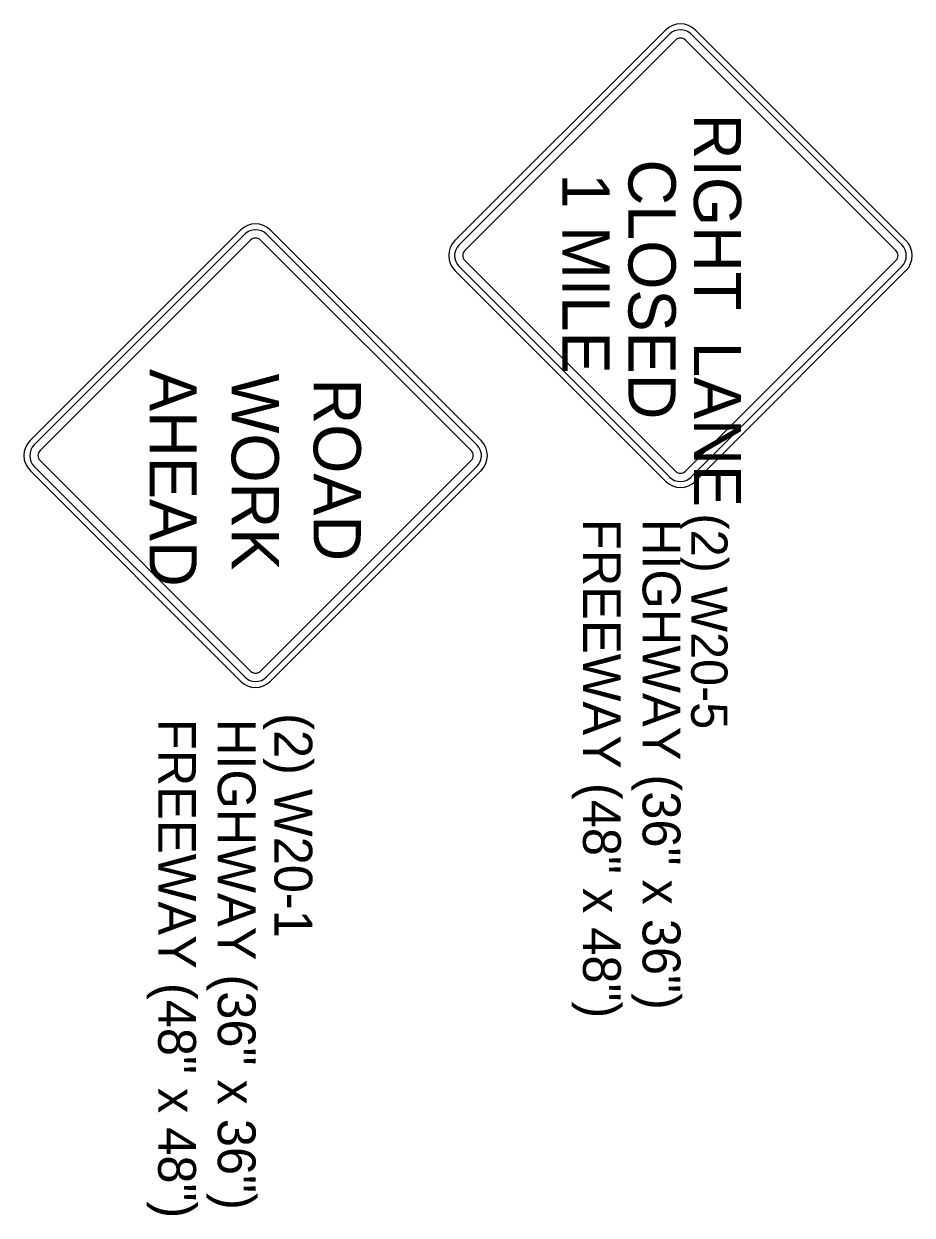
# Model space of a CAD drawing. Extents: x 1930579 to 1937521, y 596183 to 597566.
# Drawn here: x 1933840.4 to 1933981.4, y 596930.8 to 597119.9 of the extents above; entities that cross this region are included whole.
import ezdxf

# ---------------------------------------------------------------- set-up
doc = ezdxf.new("R2010")
doc.units = 0
doc.layers.add('P_TC_Signs_Temporary', color=7, linetype='Continuous')
doc.layers.add('R_Annotation', color=7, linetype='Continuous')

msp = doc.modelspace()

# ---------------------------------------------------------------- linework, layer by layer
at = {"layer": 'P_TC_Signs_Temporary'}
for p, q in [((1933908.78, 597085.51), (1933942.19, 597118.92)), ((1933909.45, 597084.85), (1933942.86, 597118.26)), ((1933910.37, 597083.92), (1933943.78, 597117.33)), ((1933945.38, 597117.33), (1933978.79, 597083.92)), ((1933946.3, 597118.26), (1933979.71, 597084.85)), ((1933946.97, 597118.92), (1933980.38, 597085.51)), ((1933841.35, 597053.77), (1933874.76, 597087.18)), ((1933879.54, 597087.18), (1933912.95, 597053.77)), ((1933842.01, 597053.11), (1933875.43, 597086.52)), ((1933842.94, 597052.18), (1933876.35, 597085.59)), ((1933877.94, 597085.59), (1933911.35, 597052.18)), ((1933878.87, 597086.52), (1933912.28, 597053.11)), ((1933942.86, 597047.99), (1933909.45, 597081.4)), ((1933943.78, 597048.92), (1933910.37, 597082.33)), ((1933978.79, 597082.33), (1933945.38, 597048.92)), ((1933979.71, 597081.4), (1933946.3, 597047.99)), ((1933942.19, 597047.33), (1933908.78, 597080.74)), ((1933980.38, 597080.74), (1933946.97, 597047.33)), ((1933875.43, 597016.25), (1933842.01, 597049.66)), ((1933876.35, 597017.18), (1933842.94, 597050.59)), ((1933911.35, 597050.59), (1933877.94, 597017.18)), ((1933912.28, 597049.66), (1933878.87, 597016.25)), ((1933874.76, 597015.58), (1933841.35, 597049)), ((1933912.95, 597049), (1933879.54, 597015.58))]:
    msp.add_line(p, q, dxfattribs=at)
for centre, radius, start, end in [((1933944.58, 597116.53), 3.37, 45, 135), ((1933944.58, 597116.53), 2.44, 45, 135), ((1933944.58, 597116.53), 1.12, 45, 135), ((1933877.15, 597084.79), 3.37, 45, 135), ((1933877.15, 597084.79), 2.44, 45, 135), ((1933877.15, 597084.79), 1.12, 45, 135), ((1933911.17, 597083.12), 3.37, 135, 225), ((1933977.99, 597083.12), 3.38, 315, 45), ((1933911.17, 597083.12), 2.44, 135, 225), ((1933911.17, 597083.12), 1.13, 135, 225), ((1933977.99, 597083.12), 1.13, 315, 45), ((1933977.99, 597083.12), 2.44, 315, 45), ((1933843.74, 597051.38), 3.37, 135, 225), ((1933843.74, 597051.38), 2.44, 135, 225), ((1933910.56, 597051.38), 2.44, 315, 45), ((1933910.56, 597051.38), 3.38, 315, 45), ((1933843.74, 597051.38), 1.13, 135, 225), ((1933910.56, 597051.38), 1.13, 315, 45), ((1933944.58, 597049.71), 3.38, 225, 315), ((1933944.58, 597049.71), 2.44, 225, 315), ((1933944.58, 597049.71), 1.12, 225, 315), ((1933877.15, 597017.97), 1.12, 225, 315), ((1933877.15, 597017.97), 3.38, 225, 315), ((1933877.15, 597017.97), 2.44, 225, 315)]:
    msp.add_arc(centre, radius, start, end, dxfattribs=at)

# ---------------------------------------------------------------- texts
for s, p in [('RIGHT\u2002LANE', (1933946.71, 597105.64)), ('CLOSED', (1933936.33, 597098.38)), ('1 MILE', (1933925.83, 597096.17)), (' AHEAD ', (1933860.32, 597067.92)), ('WORK', (1933873.34, 597064.37)), (' ROAD ', (1933886.36, 597066.4))]:
    msp.add_text(s, height=7.5, rotation=270, dxfattribs=at).set_placement(p)
at = {"layer": 'R_Annotation'}
for s, height, p in [('(2) W20-5', 5.76, (1933946.29, 597042.2)), ('FREEWAY (48" x 48")', 6, (1933929.12, 597041.34)), ('HIGHWAY (36" x 36")', 6, (1933938.58, 597041.34)), ('(2) W20-1', 6, (1933880.14, 597010.51)), ('FREEWAY (48" x 48")', 6, (1933861.69, 597009.6)), ('HIGHWAY (36" x 36")', 6, (1933871.15, 597009.6))]:
    msp.add_text(s, height=height, rotation=270, dxfattribs=at).set_placement(p)

doc.saveas('drawing.dxf')
